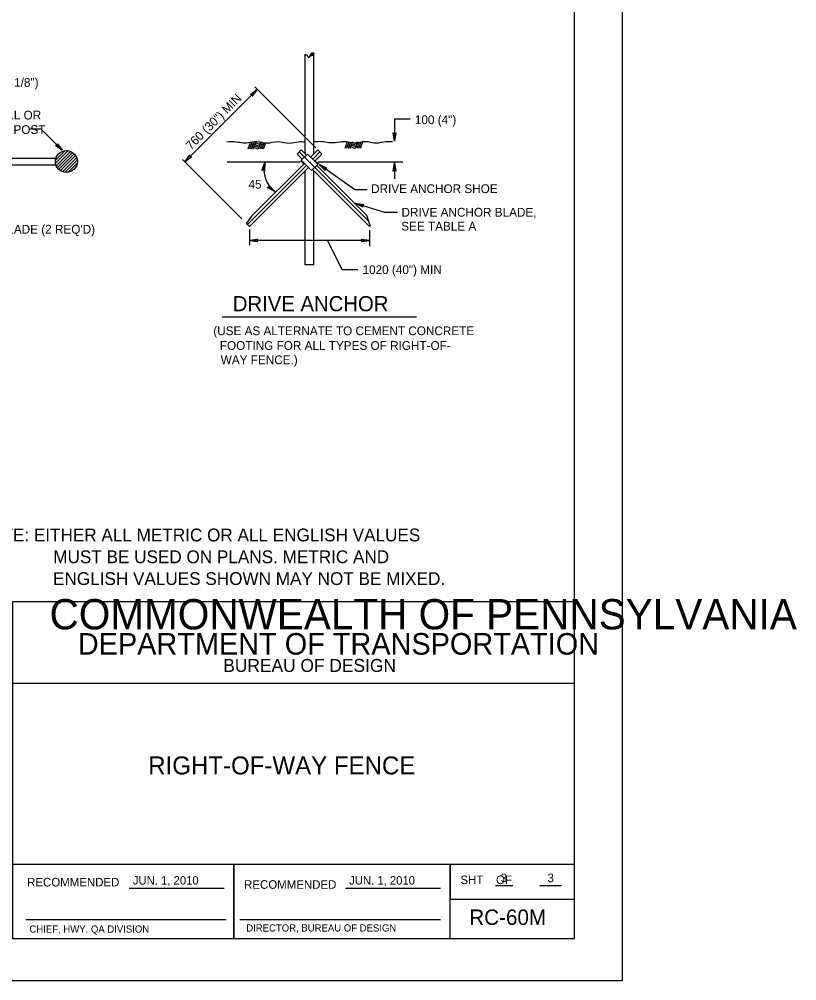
# Model space of a CAD drawing. Extents: x 13 to 918, y -903 to 879.
# Drawn here: x 639.6 to 916.4, y -903.1 to -560.6 of the extents above; entities that cross this region are included whole.
import ezdxf

# ---------------------------------------------------------------- set-up
doc = ezdxf.new("R2010")
doc.units = 0
for name, color, linetype in [('1', 7, 'Continuous'), ('2', 7, 'Continuous'), ('3', 7, 'Continuous'), ('40', 7, 'Continuous'), ('PLT-BNDY', 7, 'Continuous')]:
    doc.layers.add(name, color=color, linetype=linetype)

msp = doc.modelspace()

# ---------------------------------------------------------------- linework, layer by layer
at = {"layer": '1'}
for p, q in [((723.43825, -584.708), (745.12575, -606.39125)), ((724.3445, -585.61425), (698.56525, -611.39325)), ((773.17975, -596.1975), (773.17975, -604.06425)), ((778.80475, -596.1975), (773.17975, -596.1975)), ((721.7695, -604.612), (720.9965, -606.83925)), ((722.36525, -604.612), (721.57775, -606.88075)), ((722.961, -604.612), (722.1735, -606.88075)), ((723.557, -604.612), (722.7695, -606.88075)), ((724.86725, -606.31625), (723.1695, -605.73075)), ((725.05075, -605.785), (723.35475, -605.1955)), ((725.234, -605.25375), (723.53825, -604.66625)), ((725.43825, -604.612), (724.65275, -606.88075)), ((725.41725, -604.7225), (725.10275, -604.612)), ((726.034, -604.612), (725.2485, -606.88075)), ((726.62775, -604.612), (725.8445, -606.88075)), ((727.22575, -604.612), (726.44025, -606.88075)), ((756.3195, -604.387), (755.5465, -606.61425)), ((756.91525, -604.387), (756.12775, -606.65575)), ((757.511, -604.387), (756.7235, -606.65575)), ((758.107, -604.387), (757.3195, -606.65575)), ((759.232, -606.6225), (757.534, -606.037)), ((759.41725, -606.09125), (757.7195, -605.50575)), ((759.60075, -605.56), (757.90475, -604.9705)), ((759.784, -605.02875), (758.08825, -604.44125)), ((759.98825, -604.387), (759.20275, -606.65575)), ((759.96725, -604.4975), (759.65275, -604.387)), ((760.584, -604.387), (759.7985, -606.65575)), ((761.17775, -604.387), (760.3945, -606.65575)), ((761.77575, -604.387), (760.99025, -606.65575)), ((723.0485, -606.88075), (722.80075, -606.79325)), ((724.682, -606.8475), (722.984, -606.262)), ((740.00475, -607.158), (738.52975, -608.633)), ((738.52975, -608.633), (740.361, -610.46425)), ((739.26725, -607.8955), (763.90075, -632.52875)), ((741.81725, -609.0245), (740.00275, -610.83925)), ((740.00475, -607.158), (741.82575, -608.97875)), ((742.211, -608.63075), (741.8445, -608.9975)), ((742.211, -608.63075), (744.80075, -611.21825)), ((745.89225, -607.158), (743.332, -609.71825)), ((746.62975, -607.8955), (744.0695, -610.45575)), ((747.36725, -608.633), (744.78825, -611.212)), ((745.89225, -607.158), (747.36725, -608.633)), ((757.5985, -606.65575), (757.35075, -606.56825)), ((697.71525, -610.54325), (718.84025, -631.66625)), ((739.584, -611.57675), (713.57775, -611.57675)), ((741.836, -612.68925), (720.85075, -633.6745)), ((741.09025, -611.96), (722.25475, -630.7955)), ((739.8195, -611.0225), (740.932, -612.135)), ((739.86525, -610.97675), (740.97775, -612.08925)), ((739.911, -610.93075), (741.0235, -612.04325)), ((739.957, -610.885), (741.0695, -611.9975)), ((740.00275, -610.83925), (741.11525, -611.95175)), ((741.11525, -611.95175), (743.686, -614.5225)), ((745.8945, -612.31425), (743.686, -614.5225)), ((744.80075, -611.21825), (745.8945, -612.31425)), ((744.8465, -611.1725), (745.94025, -612.26825)), ((744.89225, -611.12675), (745.986, -612.2225)), ((744.93825, -611.08075), (746.032, -612.17675)), ((744.984, -611.035), (746.07775, -612.13075)), ((745.52575, -612.67875), (763.1945, -630.3455)), ((776.0945, -611.57675), (746.06725, -611.57675)), ((759.111, -621.40375), (746.3485, -612.34325)), ((773.17975, -611.76425), (773.17975, -617.4245)), ((742.56525, -613.435), (721.58825, -634.412)), ((744.034, -614.135), (764.309, -634.412)), ((763.46325, -621.40375), (759.111, -621.40375)), ((769.761, -629.47675), (759.334, -626.22675)), ((774.22575, -629.47675), (769.761, -629.47675)), ((722.25475, -630.7955), (720.482, -633.30575)), ((721.58825, -635.47675), (721.58825, -641.137)), ((764.309, -635.75575), (764.309, -641.41825)), ((764.309, -639.437), (721.58825, -639.437)), ((744.511, -648.035), (741.386, -648.035)), ((760.13825, -649.81825), (754.51325, -649.81825)), ((809.116, -869.09675), (815.258, -869.09675)), ((824.9255, -869.09675), (832.572, -869.09675)), ((678.7155, -870.08075), (712.602, -870.08075)), ((755.7135, -870.08075), (789.5835, -870.08075)), ((642.0125, -881.26844), (713.262, -881.26844)), ((718.182, -881.26844), (789.522, -881.26844))]:
    msp.add_line(p, q, dxfattribs=at)
msp.add_lwpolyline([(837.2505, -888.06975), (837.2505, -324.06975), (51.2505, -324.06975), (51.2505, -888.06975), (837.2505, -888.06975), (837.2505, -861.71075), (637.2505, -861.71075), (637.2505, -797.03325), (837.2505, -797.03325), (837.2505, -768.06975), (637.2505, -768.06975), (637.2505, -888.06975), (716.052, -888.06975), (716.052, -861.71075), (716.052, -888.06975), (793.052, -888.06975), (793.052, -861.71075), (793.052, -874.02725), (837.2505, -874.02725)], dxfattribs=at)
at = {"layer": '3'}
for p, q in [((741.386, -608.56825), (741.386, -573.035)), ((743.82575, -573.36425), (744.107, -573.25175)), ((744.02975, -573.1475), (744.32775, -572.9245)), ((744.06725, -573.1995), (744.36525, -572.97675)), ((744.107, -573.25175), (744.40475, -573.02875)), ((744.511, -608.512), (744.511, -573.035)), ((643.0785, -599.6545), (647.24525, -599.6545)), ((647.24525, -599.6545), (654.841, -607.2525)), ((652.54525, -610.76925), (655.85575, -607.45875)), ((652.57025, -611.8525), (657.014, -607.40875)), ((652.8285, -612.69825), (657.83075, -607.69625)), ((653.191, -613.44425), (658.562, -608.07325)), ((653.69725, -614.042), (659.14325, -608.59625)), ((654.3265, -614.52125), (659.6535, -609.19425)), ((558.7265, -610.12125), (652.69525, -610.12125)), ((558.7265, -612.467), (652.69525, -612.467)), ((652.4765, -612.467), (652.4765, -610.12125)), ((655.0265, -614.9295), (660.016, -609.94)), ((655.91825, -615.142), (660.23075, -610.8295)), ((657.04525, -615.12325), (660.137, -612.03175)), ((742.9485, -611.57675), (742.9485, -611.57675)), ((741.386, -648.035), (741.386, -614.56625)), ((744.511, -648.035), (744.511, -614.64125)), ((720.85075, -633.6745), (720.482, -633.30575)), ((763.1945, -630.3455), (764.4735, -634.2975)), ((721.58825, -634.412), (720.85075, -633.6745)), ((764.309, -634.412), (764.4485, -634.2725)), ((749.36325, -639.51625), (754.51325, -649.81825)), ((711.89225, -666.65575), (781.06725, -666.65575))]:
    msp.add_line(p, q, dxfattribs=at)
for points in [[(741.386, -573.035), (741.78825, -573.28925), (742.05075, -573.47675), (742.27575, -573.758), (742.4985, -574.01825), (742.59225, -574.28075), (742.911, -574.037), (743.209, -573.7955), (743.49025, -573.6455), (743.807, -573.47675), (744.08825, -573.36425), (744.311, -573.233), (744.511, -573.035), (744.461, -572.86), (744.32975, -572.72875), (744.16325, -572.69125), (743.9945, -572.6725), (743.67575, -572.7475), (743.41525, -572.9725), (743.30275, -573.17875), (743.07775, -573.533), (742.92975, -573.7955), (742.7985, -573.9995), (742.611, -574.2995)], [(742.836, -574.05575), (743.059, -573.7205), (743.3215, -573.28925), (743.4715, -573.06625), (743.6195, -572.86), (743.732, -572.8225), (743.93825, -572.7475), (744.107, -572.7475), (744.29225, -572.80375), (744.4235, -572.87875), (744.4235, -573.02875)], [(742.89025, -574.09125), (743.11325, -573.75575), (743.37575, -573.3245), (743.52575, -573.10375), (743.659, -572.91425), (743.75275, -572.883), (743.9485, -572.812), (744.0965, -572.812), (744.26725, -572.86425), (744.359, -572.91625), (744.359, -573.02875)], [(743.15275, -573.81425), (743.1695, -573.79125), (743.432, -573.36), (743.57775, -573.14125), (743.70075, -572.9705), (743.77575, -572.9455), (743.961, -572.87675), (744.08825, -572.87675), (744.24025, -572.9245), (744.2945, -572.95375), (744.2945, -573.02875)], [(743.309, -573.683), (743.486, -573.39325), (743.632, -573.17675), (743.74025, -573.0245), (743.7965, -573.00575), (743.9715, -572.94325), (744.07775, -572.94325), (744.21525, -572.985), (744.22775, -572.99125), (744.22775, -573.02875)], [(743.38825, -573.67875), (743.54025, -573.42875), (743.686, -573.21425), (743.782, -573.08075), (743.81725, -573.06825), (743.984, -573.008), (744.06725, -573.008), (744.16325, -573.037)], [(743.4735, -573.66425), (743.5945, -573.46425), (743.73825, -573.25175), (743.8215, -573.135), (743.83825, -573.12875), (743.9945, -573.0725), (744.059, -573.0725), (744.0985, -573.085)], [(743.6715, -573.46825), (743.79225, -573.28925), (743.86325, -573.18925), (744.007, -573.137), (744.034, -573.137)], [(743.75275, -573.46425), (743.8445, -573.32675), (743.90475, -573.24325), (743.9695, -573.2205)], [(722.086, -587.36825), (722.30475, -587.43925), (724.3445, -585.61425), (722.086, -587.36825), (721.8945, -587.383), (724.3445, -585.61425), (722.509, -587.63925), (722.582, -587.85375), (724.3445, -585.61425), (722.5695, -588.06), (722.582, -587.85375)], [(773.536, -601.22675), (773.32975, -601.333), (773.17975, -604.06425), (773.536, -601.22675), (773.661, -601.08075), (773.17975, -604.06425), (773.0445, -601.335), (772.84225, -601.235), (773.17975, -604.06425), (772.70475, -601.08075), (772.84225, -601.235)], [(653.2035, -605.14425), (653.137, -605.3505), (654.841, -607.2525), (653.2035, -605.14425), (653.189, -604.965), (654.841, -607.2525), (652.9515, -605.54), (652.7515, -605.60875), (654.841, -607.2525), (652.55975, -605.59625), (652.7515, -605.60875)], [(700.8235, -609.63925), (700.60475, -609.56825), (698.56525, -611.39325), (700.8235, -609.63925), (701.01525, -609.6245), (698.56525, -611.39325), (700.40075, -609.36825), (700.32775, -609.15375), (698.56525, -611.39325), (700.34025, -608.9475), (700.32775, -609.15375)], [(726.107, -614.36625), (726.32975, -614.30575), (727.06525, -611.6705), (726.107, -614.36625), (725.95475, -614.48075), (727.06525, -611.6705), (726.611, -614.36625), (726.78825, -614.50575), (727.06525, -611.6705), (726.886, -614.685), (726.78825, -614.50575)], [(748.457, -614.27675), (748.48825, -614.0475), (746.3485, -612.34325), (748.457, -614.27675), (748.50275, -614.462), (746.3485, -612.34325), (748.65275, -613.81425), (748.85275, -613.70575), (746.3485, -612.34325), (749.05475, -613.683), (748.85275, -613.70575)], [(772.8235, -614.60175), (773.02975, -614.4955), (773.17975, -611.76425), (772.8235, -614.60175), (772.6985, -614.7475), (773.17975, -611.76425), (773.31525, -614.49325), (773.51725, -614.59325), (773.17975, -611.76425), (773.65475, -614.7475), (773.51725, -614.59325)], [(728.536, -619.9455), (728.49025, -620.1725), (730.54025, -621.985), (728.536, -619.9455), (728.4985, -619.758), (730.54025, -621.985), (728.31525, -620.3975), (728.111, -620.4955), (730.54025, -621.985), (727.907, -620.50575), (728.111, -620.4955)], [(761.93825, -627.412), (761.8985, -627.183), (759.334, -626.22675), (761.93825, -627.412), (762.04025, -627.5725), (759.334, -626.22675), (761.97975, -626.91), (762.136, -626.7455), (759.334, -626.22675), (762.3235, -626.662), (762.136, -626.7455)], [(724.42575, -639.79325), (724.3195, -639.587), (721.58825, -639.437), (724.42575, -639.79325), (724.5715, -639.91825), (721.58825, -639.437), (724.31725, -639.30175), (724.41725, -639.0995), (721.58825, -639.437), (724.5715, -638.962), (724.41725, -639.0995)], [(761.4715, -639.08075), (761.57775, -639.287), (764.309, -639.437), (761.4715, -639.08075), (761.32575, -638.95575), (764.309, -639.437), (761.57975, -639.5725), (761.47975, -639.7745), (764.309, -639.437), (761.32575, -639.912), (761.47975, -639.7745)]]:
    msp.add_lwpolyline(points, dxfattribs=at)
msp.add_circle((656.38489, -611.29412), 3.9075, dxfattribs=at)
msp.add_arc((736.44623, -614.25258), 9.72983, 164.6098139, 232.6276972, dxfattribs=at)
for points in [[(713.5215, -604.285), (716.19025, -604.17675), (718.80475, -604.55175), (721.086, -604.55175), (724.18825, -604.17675), (727.77575, -604.662), (731.811, -604.17675), (735.71525, -604.737), (739.061, -604.233), (741.41525, -604.28925)], [(744.55175, -604.217), (747.2205, -604.10875), (749.835, -604.48375), (752.11625, -604.48375), (755.2185, -604.10875), (758.806, -604.594), (762.84125, -604.10875), (766.7455, -604.669), (770.09125, -604.165), (772.4455, -604.22125)]]:
    msp.add_spline(points, degree=3, dxfattribs=at)
at = {"layer": 'PLT-BNDY'}
msp.add_lwpolyline([(13.2505, -309.06975), (854.2505, -309.06975), (854.2505, -903.06975), (13.2505, -903.06975)], close=True, dxfattribs=at)

# ---------------------------------------------------------------- texts
at = {"layer": '1'}
for s, height, p in [('COMMONWEALTH OF PENNSYLVANIA', 10.7833725, (650.4015, -777.92625)), ('DEPARTMENT OF TRANSPORTATION', 7.6842885, (660.4625, -786.9205)), ('BUREAU OF DESIGN', 4.6220925, (712.237, -793.08275)), ('RIGHT-OF-WAY FENCE', 6.4000005, (685.521, -829.57375)), ('RECOMMENDED', 3.048, (642.414, -869.47625)), ('JUN. 1, 2010', 3, (680.05403, -868.81375)), ('JUN. 1, 2010', 3, (757.05203, -868.81375)), ('SHT    OF', 3.048, (796.656, -868.63975)), ('RECOMMENDED', 3.048, (719.658, -870.3125)), ('APPROVED', 0.019212, (680.2735, -870.13825)), ('RC-60M', 5.500001, (799.78225, -883.18475)), ('CHIEF, HWY. QA DIVISION', 2.5399995, (643.22964, -885.92516)), ('DIRECTOR, BUREAU OF DESIGN', 2.5399995, (720.41164, -885.52644))]:
    msp.add_text(s, height=height, dxfattribs=at).set_placement(p)
at = {"layer": '2'}
for p in [(811.026, -867.961), (827.64125, -867.961)]:
    msp.add_text('3', height=3.048, dxfattribs=at).set_placement(p)
at = {"layer": '3'}
for s, height, p in [('(    1 1/2" x 1 1/2" x 1/8")', 3.1249995, (601.386, -584.676)), ('END, PULL OR', 3.1249995, (618.3995, -596.31925)), ('100 (4")', 3.124999, (780.44, -597.977)), ('CORNER POST', 3.1249995, (618.3015, -601.492)), ('.', 3.125, (742.732, -611.887)), ('45', 3.124999, (721.209, -620.95175)), ('DRIVE ANCHOR SHOE', 3.1249995, (764.85275, -622.53925)), ('DRIVE ANCHOR BLADE,', 3.1249995, (775.6695, -630.92875)), ('SEE TABLE A', 3.1249995, (775.584, -635.8975)), ("DRIVE ANCHOR BLADE (2 REQ'D)", 3.1249995, (599.3745, -636.9775)), ('.', 3.125, (749.1215, -639.758)), ('1020 (40") MIN', 3.1249995, (761.81225, -651.3705)), ('DRIVE ANCHOR', 5.4020865, (715.62975, -664.6205)), ('(USE AS ALTERNATE TO CEMENT CONCRETE', 3.1249995, (708.684, -673.13925)), ('FOOTING FOR ALL TYPES OF RIGHT-OF-', 3.1249995, (711.0195, -678.39125)), ('WAY FENCE.)', 3.1249995, (711.32975, -683.4725))]:
    msp.add_text(s, height=height, dxfattribs=at).set_placement(p)
msp.add_text('760 (30") MIN', height=3.1249995, rotation=45, dxfattribs=at).set_placement((700.72775, -607.3765))
at = {"layer": '40'}
for s, p in [('NOTE: EITHER ALL METRIC OR ALL ENGLISH VALUES', (624.4995, -746.581)), ('MUST BE USED ON PLANS. METRIC AND', (651.72425, -754.349)), ('ENGLISH VALUES SHOWN MAY NOT BE MIXED.', (651.65175, -762.11725))]:
    msp.add_text(s, height=4.558749, dxfattribs=at).set_placement(p)

doc.saveas('drawing.dxf')
